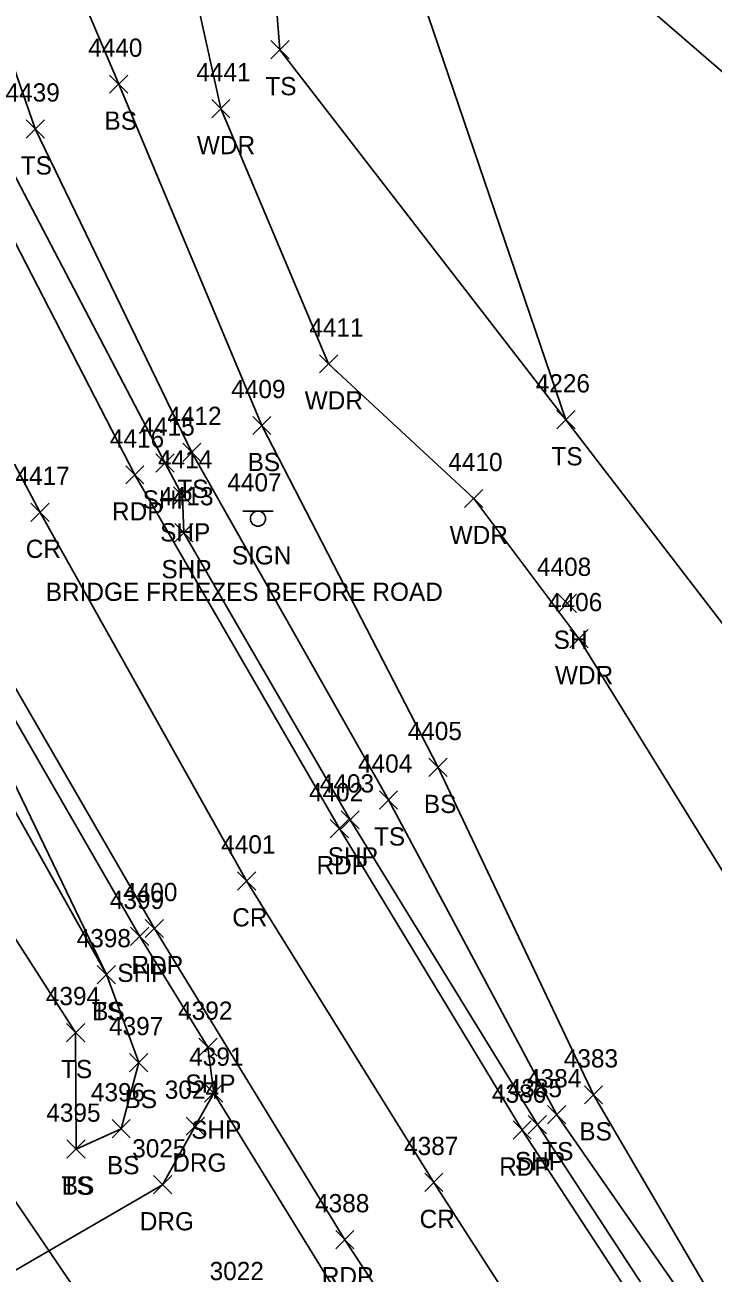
# Model space of a CAD drawing. Extents: x 1601151 to 1602912, y 499508 to 501770.
# Drawn here: x 1601811.7 to 1601887.2, y 499859.1 to 499996 of the extents above; entities that cross this region are included whole.
import ezdxf

# ---------------------------------------------------------------- set-up
doc = ezdxf.new("R2010")
doc.units = 0
for name, color, linetype in [('L_A', 7, 'Continuous'), ('L_I', 7, 'Continuous'), ('L_TIC', 7, 'Continuous'), ('LAWA', 7, 'Continuous'), ('LELB', 7, 'Continuous'), ('P_A', 7, 'Continuous'), ('P_I', 7, 'Continuous'), ('P_TIC', 7, 'Continuous'), ('PET', 7, 'Continuous'), ('PRC', 7, 'Continuous'), ('PSP', 7, 'Continuous'), ('R_A', 7, 'Continuous'), ('R_I', 7, 'Continuous'), ('R_TIC', 7, 'Continuous'), ('RDG', 7, 'Continuous'), ('S_A', 7, 'Continuous'), ('S_C', 7, 'Continuous'), ('S_I', 7, 'Continuous'), ('SSGN', 7, 'Continuous'), ('UCO', 7, 'Continuous')]:
    doc.layers.add(name, color=color, linetype=linetype)

msp = doc.modelspace()

# ---------------------------------------------------------------- linework, layer by layer
at = {"layer": 'L_TIC'}
for points in [[(1601838.67, 499992.25), (1601840.67, 499994.25)], [(1601840.67, 499992.25), (1601838.67, 499994.25)], [(1601820.99, 499988.47), (1601822.99, 499990.47)], [(1601822.99, 499988.47), (1601820.99, 499990.47)], [(1601832.19, 499985.79), (1601834.19, 499987.79)], [(1601834.19, 499985.79), (1601832.19, 499987.79)], [(1601811.84, 499983.56), (1601813.84, 499985.56)], [(1601813.84, 499983.56), (1601811.84, 499985.56)], [(1601844.01, 499957.8), (1601846.01, 499959.8)], [(1601846.01, 499957.8), (1601844.01, 499959.8)], [(1601836.68, 499951.04), (1601838.68, 499953.04)], [(1601838.68, 499951.04), (1601836.68, 499953.04)], [(1601870.03, 499951.67), (1601872.03, 499953.67)], [(1601872.03, 499951.67), (1601870.03, 499953.67)], [(1601829.01, 499948.1), (1601831.01, 499950.1)], [(1601831.01, 499948.1), (1601829.01, 499950.1)], [(1601859.91, 499943.04), (1601861.91, 499945.04)], [(1601861.91, 499943.04), (1601859.91, 499945.04)], [(1601870.19, 499931.55), (1601872.19, 499933.55)], [(1601872.19, 499931.55), (1601870.19, 499933.55)], [(1601871.45, 499927.68), (1601873.45, 499929.68)], [(1601873.45, 499927.68), (1601871.45, 499929.68)], [(1601856.01, 499913.55), (1601858.01, 499915.55)], [(1601858.01, 499913.55), (1601856.01, 499915.55)], [(1601850.57, 499909.98), (1601852.57, 499911.98)], [(1601852.57, 499909.98), (1601850.57, 499911.98)], [(1601819.64, 499890.83), (1601821.64, 499892.83)], [(1601821.64, 499890.83), (1601819.64, 499892.83)], [(1601819.64, 499890.83), (1601821.64, 499892.83)], [(1601821.64, 499890.83), (1601819.64, 499892.83)], [(1601816.26, 499884.48), (1601818.26, 499886.48)], [(1601818.26, 499884.48), (1601816.26, 499886.48)], [(1601823.19, 499881.19), (1601825.19, 499883.19)], [(1601825.19, 499881.19), (1601823.19, 499883.19)], [(1601873.05, 499877.65), (1601875.05, 499879.65)], [(1601875.05, 499877.65), (1601873.05, 499879.65)], [(1601869.02, 499875.47), (1601871.02, 499877.47)], [(1601871.02, 499875.47), (1601869.02, 499877.47)], [(1601821.26, 499873.94), (1601823.26, 499875.94)], [(1601823.26, 499873.94), (1601821.26, 499875.94)], [(1601816.31, 499871.7), (1601818.31, 499873.7)], [(1601818.31, 499871.7), (1601816.31, 499873.7)], [(1601816.31, 499871.7), (1601818.31, 499873.7)], [(1601818.31, 499871.7), (1601816.31, 499873.7)]]:
    msp.add_lwpolyline(points, dxfattribs=at)
at = {"layer": 'LAWA'}
msp.add_lwpolyline([(1602022.55, 499813.65), (1601986.23, 499821.98), (1601948.47, 499842.78), (1601932.99, 499850.05), (1601908.71, 499876.98), (1601895.51, 499891.37), (1601872.45, 499928.68), (1601860.91, 499944.04), (1601845.01, 499958.8), (1601833.19, 499986.79), (1601825.63, 500021.05), (1601823.16, 500036.28), (1601824.01, 500062.73), (1601813.25, 500083.11), (1601795.9, 500116.91), (1601787.61, 500146.09), (1601789.07, 500162.65), (1601789.86, 500175.08), (1601780.36, 500177.88), (1601766.38, 500200.64), (1601744.62, 500238.97)], dxfattribs=at)
at = {"layer": 'LELB'}
for points in [[(1601817.31, 499872.7), (1601822.26, 499874.94), (1601824.19, 499882.19), (1601820.64, 499891.83), (1601797.18, 499933.64), (1601778.06, 499967.49), (1601759.63, 500004.16), (1601735.92, 500054.97), (1601725.84, 500087), (1601715.25, 500119.3), (1601698.06, 500177.62), (1601684.73, 500227.08), (1601672.09, 500269.9), (1601659.22, 500313.1), (1601655.82, 500330.46)], [(1601820.64, 499891.83), (1601799.69, 499935.32), (1601781.01, 499969.12), (1601762.54, 500005.3), (1601740.72, 500057.2), (1601729.05, 500088.56), (1601717.64, 500121.66), (1601699.62, 500177.82), (1601686.02, 500227.23), (1601673.93, 500270.73), (1601661.95, 500313.91), (1601655.82, 500330.46)], [(1601931.2, 499782.14), (1601903.71, 499827.94), (1601870.02, 499876.47), (1601851.57, 499910.98), (1601830.01, 499949.1), (1601812.84, 499984.56), (1601799.79, 500022.21), (1601775.51, 500071.18), (1601768.77, 500104.65), (1601752.69, 500132.35), (1601745.59, 500147.03), (1601736.89, 500188.62), (1601718.63, 500236.24), (1601706.47, 500280.22)], [(1601903.71, 499827.94), (1601874.05, 499878.65), (1601857.01, 499914.55), (1601837.68, 499952.04), (1601821.99, 499989.47), (1601806.47, 500025.9), (1601786.77, 500075.31), (1601776.8, 500108.45), (1601758.74, 500135.39), (1601750.45, 500149.06), (1601745.01, 500191.77), (1601725.55, 500237.57)], [(1601839.67, 499993.25), (1601837.76, 500017.47), (1601833.53, 500022.48), (1601829.43, 500037.77), (1601824.01, 500062.73)], [(1601871.03, 499952.67), (1601838.6, 500047.83)], [(1601869.01, 500018.88), (1601869.51, 500006.98), (1601901.98, 499978.89), (1601950.31, 499963.52), (1601960.93, 499964.27)], [(1601839.67, 499993.25), (1601871.03, 499952.67)], [(1601871.03, 499952.67), (1601917.68, 499891.97)], [(1601800.97, 499910.85), (1601817.26, 499885.48), (1601817.31, 499872.7)]]:
    msp.add_lwpolyline(points, dxfattribs=at)
at = {"layer": 'P_TIC'}
for points in [[(1601826.07, 499946.93), (1601828.07, 499948.93)], [(1601828.07, 499946.93), (1601826.07, 499948.93)], [(1601822.76, 499945.63), (1601824.76, 499947.63)], [(1601824.76, 499945.63), (1601822.76, 499947.63)], [(1601828, 499943.33), (1601830, 499945.33)], [(1601830, 499943.33), (1601828, 499945.33)], [(1601812.37, 499941.52), (1601814.37, 499943.52)], [(1601814.37, 499941.52), (1601812.37, 499943.52)], [(1601828.13, 499939.29), (1601830.13, 499941.29)], [(1601830.13, 499939.29), (1601828.13, 499941.29)], [(1601845.19, 499906.84), (1601847.19, 499908.84)], [(1601847.19, 499906.84), (1601845.19, 499908.84)], [(1601846.37, 499907.8), (1601848.37, 499909.8)], [(1601848.37, 499907.8), (1601846.37, 499909.8)], [(1601835.01, 499901.11), (1601837.01, 499903.11)], [(1601837.01, 499901.11), (1601835.01, 499903.11)], [(1601824.9, 499895.89), (1601826.9, 499897.89)], [(1601826.9, 499895.89), (1601824.9, 499897.89)], [(1601823.29, 499895.03), (1601825.29, 499897.03)], [(1601825.29, 499895.03), (1601823.29, 499897.03)], [(1601830.77, 499882.88), (1601832.77, 499884.88)], [(1601832.77, 499882.88), (1601830.77, 499884.88)], [(1601831.41, 499877.84), (1601833.41, 499879.84)], [(1601833.41, 499877.84), (1601831.41, 499879.84)], [(1601866.9, 499874.39), (1601868.9, 499876.39)], [(1601868.9, 499874.39), (1601866.9, 499876.39)], [(1601865.23, 499873.79), (1601867.23, 499875.79)], [(1601867.23, 499873.79), (1601865.23, 499875.79)], [(1601855.54, 499868.05), (1601857.54, 499870.05)], [(1601857.54, 499868.05), (1601855.54, 499870.05)], [(1601845.78, 499861.77), (1601847.78, 499863.77)], [(1601847.78, 499861.77), (1601845.78, 499863.77)]]:
    msp.add_lwpolyline(points, dxfattribs=at)
at = {"layer": 'PET'}
for points in [[(1601995.67, 499683.24), (1601967.44, 499723.89), (1601951.2, 499747.81), (1601928.38, 499780.82), (1601898.7, 499825.12), (1601866.23, 499874.79), (1601846.19, 499907.84), (1601823.76, 499946.63), (1601805.55, 499981.9), (1601788.87, 500017.29), (1601766.92, 500067.61), (1601755.39, 500098.81), (1601743.92, 500129.72), (1601726.45, 500185.71), (1601711.93, 500234.21), (1601699.42, 500278.31), (1601688.33, 500319.61), (1601682.56, 500342.8), (1601675.53, 500367.54), (1601665.76, 500404.47), (1601656.17, 500441.2), (1601643.95, 500489.36), (1601630.25, 500541.68)], [(1601976.03, 499671.31), (1601949.07, 499710.22), (1601932.5, 499734.59), (1601906.16, 499773.6), (1601879.17, 499813.54), (1601846.78, 499862.77), (1601825.9, 499896.89), (1601802.83, 499936.77), (1601785.08, 499971.15), (1601767.41, 500007.57), (1601745.41, 500058.72), (1601733.84, 500089.25), (1601721.8, 500122.71), (1601703.99, 500178.99), (1601689.71, 500228.27), (1601677.58, 500272.25), (1601666.12, 500315.05), (1601653.43, 500363.86), (1601644.59, 500397.8), (1601635.03, 500435.31), (1601622.92, 500483.99), (1601609.64, 500536.46)]]:
    msp.add_lwpolyline(points, dxfattribs=at)
at = {"layer": 'PRC'}
msp.add_lwpolyline([(1601985.39, 499677.47), (1601958.56, 499716.67), (1601942.32, 499739.6), (1601916.26, 499778.51), (1601888.68, 499819.15), (1601856.54, 499869.05), (1601836.01, 499902.11), (1601813.37, 499942.52), (1601794.98, 499977.03), (1601778.27, 500012.72), (1601755.57, 500062.85), (1601744.49, 500093.78), (1601732.77, 500126.07), (1601715.37, 500182.36), (1601700.57, 500231.28), (1601688.37, 500275.57), (1601676.78, 500317.03), (1601664.23, 500365.85), (1601655.24, 500401.01), (1601645.63, 500438.14), (1601632.99, 500486.74), (1601619.53, 500538.88)], dxfattribs=at)
at = {"layer": 'PSP'}
for points in [[(1601997, 499684.27), (1601969.14, 499725.42), (1601931.2, 499782.14), (1601900.18, 499826.03), (1601867.9, 499875.39), (1601847.37, 499908.8), (1601829.13, 499940.29), (1601829, 499944.33), (1601827.07, 499947.93), (1601808.69, 499983.01), (1601791.36, 500018.61), (1601769.33, 500068.57), (1601758.08, 500099.65), (1601747.15, 500130.33), (1601730.42, 500186.97), (1601714.57, 500235.16), (1601709.05, 500248.69), (1601701, 500279.76), (1601693.52, 500306.69)], [(1601974.74, 499670.12), (1601948.09, 499709.66), (1601931.04, 499733.86), (1601904.81, 499772.45), (1601877.68, 499812.76), (1601851.66, 499852.31), (1601848.35, 499852.94), (1601832.41, 499878.84), (1601831.77, 499883.88), (1601824.29, 499896.03), (1601801.22, 499936.03), (1601783.34, 499970.29), (1601765.73, 500006.71), (1601743.28, 500058.03), (1601731.38, 500088.89), (1601719.94, 500122.25), (1601702, 500178.56), (1601687.75, 500227.8), (1601675.97, 500271.58)], [(1601830.38, 499875.22), (1601832.41, 499878.84)]]:
    msp.add_lwpolyline(points, dxfattribs=at)
at = {"layer": 'R_TIC'}
for points in [[(1601829.38, 499874.22), (1601831.38, 499876.22)], [(1601831.38, 499874.22), (1601829.38, 499876.22)], [(1601825.81, 499867.79), (1601827.81, 499869.79)], [(1601827.81, 499867.79), (1601825.81, 499869.79)]]:
    msp.add_lwpolyline(points, dxfattribs=at)
at = {"layer": 'RDG'}
msp.add_lwpolyline([(1601830.38, 499875.22), (1601826.81, 499868.79), (1601807.74, 499857.74), (1601789.49, 499846.65), (1601768.85, 499838.86), (1601747.32, 499836.92), (1601727.43, 499838.27), (1601705.37, 499845.09), (1601686.43, 499853.19), (1601664.54, 499867.85), (1601655.98, 499874.72), (1601624.93, 499904.1), (1601578.24, 499947.21)], dxfattribs=at)
at = {"layer": 'SSGN'}
for p, q in [((1601835.61, 499942.66), (1601838.94, 499942.66)), ((1601837.26, 499941.83), (1601837.26, 499941.83))]:
    msp.add_line(p, q, dxfattribs=at)
msp.add_circle((1601837.26, 499941.83), 0.833, dxfattribs=at)
at = {"layer": 'UCO'}
msp.add_lwpolyline([(1601777.6, 499915.52), (1601910.46, 499720.23)], dxfattribs=at)

# ---------------------------------------------------------------- texts
at = {"layer": 'L_A'}
for s, p in [('TS', (1601838.07, 499988.25)), ('BS', (1601820.43, 499984.47)), ('WDR', (1601830.56, 499981.79)), ('TS', (1601811.25, 499979.56)), ('WDR', (1601842.38, 499953.8)), ('BS', (1601836.12, 499947.04)), ('TS', (1601869.44, 499947.67)), ('TS', (1601828.42, 499944.1)), ('WDR', (1601858.27, 499939.04)), ('SH', (1601869.68, 499927.55)), ('WDR', (1601869.82, 499923.68)), ('BS', (1601855.45, 499909.55)), ('TS', (1601849.98, 499905.98)), ('TS', (1601819.05, 499886.83)), ('BS', (1601819.08, 499886.83)), ('TS', (1601815.67, 499880.48)), ('BS', (1601822.63, 499877.19)), ('BS', (1601872.49, 499873.65)), ('TS', (1601868.43, 499871.47)), ('BS', (1601820.7, 499869.94)), ('TS', (1601815.72, 499867.7)), ('BS', (1601815.75, 499867.7))]:
    msp.add_text(s, height=2, dxfattribs=at).set_placement(p)
at = {"layer": 'L_I'}
for s, p in [('4440', (1601818.64, 499992.47)), ('4441', (1601830.5, 499989.79)), ('4439', (1601809.58, 499987.56)), ('4411', (1601842.89, 499961.8)), ('4409', (1601834.33, 499955.04)), ('4226', (1601867.71, 499955.67)), ('4412', (1601827.32, 499952.1)), ('4410', (1601858.13, 499947.04)), ('4408', (1601867.85, 499935.55)), ('4406', (1601869.06, 499931.68)), ('4405', (1601853.67, 499917.55)), ('4404', (1601848.23, 499913.98)), ('4398', (1601817.38, 499894.83)), ('4398', (1601817.38, 499894.83)), ('4394', (1601814, 499888.48)), ('4397', (1601820.93, 499885.19)), ('4383', (1601870.79, 499881.65)), ('4384', (1601866.76, 499879.47)), ('4396', (1601818.94, 499877.94)), ('4395', (1601814.05, 499875.7)), ('4395', (1601814.05, 499875.7))]:
    msp.add_text(s, height=2, dxfattribs=at).set_placement(p)
at = {"layer": 'P_A'}
for s, p in [('SHP', (1601824.61, 499942.93)), ('RDP', (1601821.25, 499941.63)), ('SHP', (1601826.53, 499939.33)), ('CR', (1601811.8, 499937.52)), ('SHP', (1601826.67, 499935.29)), ('RDP', (1601843.68, 499902.84)), ('SHP', (1601844.91, 499903.8)), ('CR', (1601834.44, 499897.11)), ('RDP', (1601823.39, 499891.89)), ('SHP', (1601821.83, 499891.03)), ('SHP', (1601829.3, 499878.88)), ('SHP', (1601829.94, 499873.84)), ('SHP', (1601865.43, 499870.39)), ('RDP', (1601863.71, 499869.79)), ('CR', (1601854.98, 499864.05)), ('RDP', (1601844.26, 499857.77))]:
    msp.add_text(s, height=2, dxfattribs=at).set_placement(p)
at = {"layer": 'P_I'}
for s, p in [('4415', (1601824.38, 499950.93)), ('4416', (1601821.02, 499949.63)), ('4414', (1601826.3, 499947.33)), ('4417', (1601810.67, 499945.52)), ('4413', (1601826.44, 499943.29)), ('4403', (1601844.04, 499911.8)), ('4402', (1601842.85, 499910.84)), ('4401', (1601833.23, 499905.11)), ('4399', (1601821.02, 499899.03)), ('4400', (1601822.48, 499899.89)), ('4392', (1601828.51, 499886.88)), ('4391', (1601829.72, 499881.84)), ('4385', (1601864.64, 499878.39)), ('4386', (1601862.91, 499877.79)), ('4387', (1601853.28, 499872.05)), ('4388', (1601843.52, 499865.77))]:
    msp.add_text(s, height=2, dxfattribs=at).set_placement(p)
at = {"layer": 'R_A'}
for p in [(1601827.86, 499870.22), (1601824.3, 499863.79)]:
    msp.add_text('DRG', height=2, dxfattribs=at).set_placement(p)
at = {"layer": 'R_I'}
for s, p in [('3024', (1601827.04, 499878.22)), ('3025', (1601823.47, 499871.79)), ('3022', (1601831.96, 499858.33))]:
    msp.add_text(s, height=2, dxfattribs=at).set_placement(p)
at = {"layer": 'S_A'}
msp.add_text('SIGN', height=2, dxfattribs=at).set_placement((1601834.39, 499936.81))
at = {"layer": 'S_C'}
msp.add_text('BRIDGE FREEZES BEFORE ROAD', height=2, dxfattribs=at).set_placement((1601813.99, 499932.81))
at = {"layer": 'S_I'}
msp.add_text('4407', height=2, dxfattribs=at).set_placement((1601833.9, 499944.81))

doc.saveas('drawing.dxf')
